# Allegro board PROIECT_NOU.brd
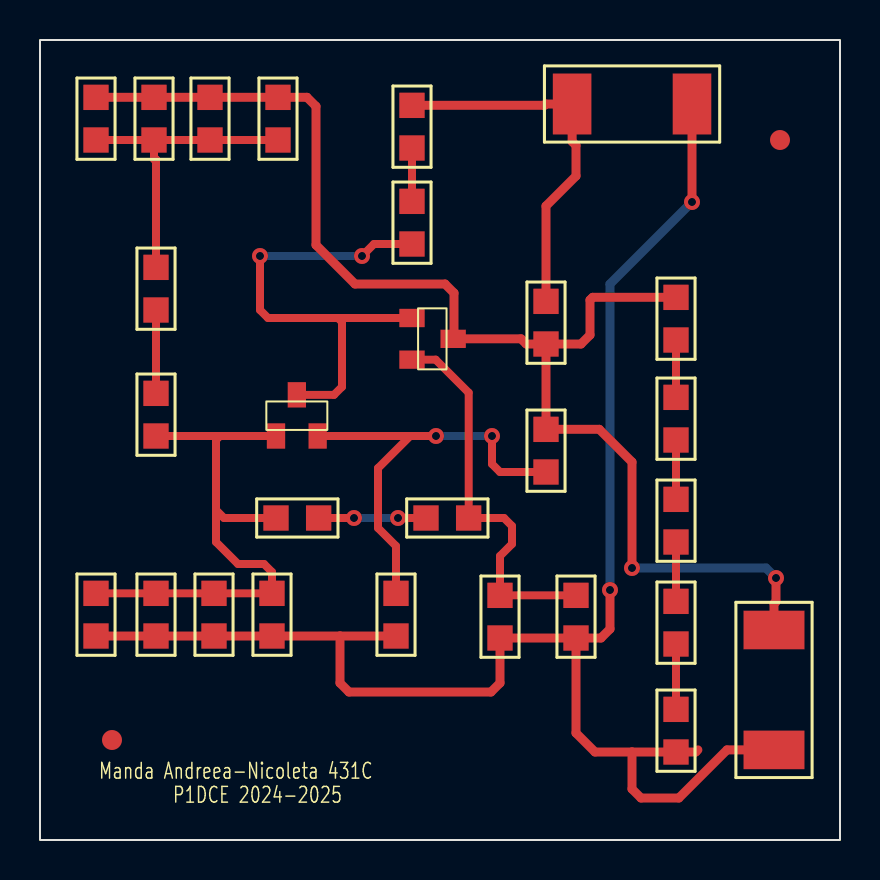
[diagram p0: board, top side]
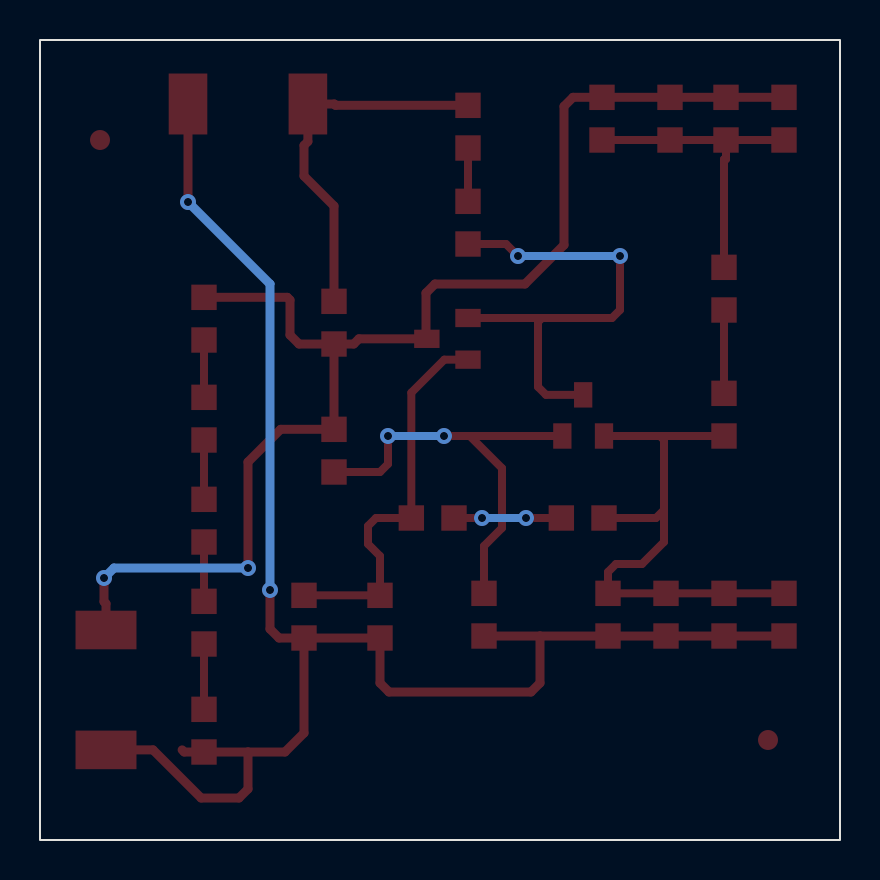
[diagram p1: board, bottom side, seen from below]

Outline 40 x 40 mm; copper layers: TOP, BOTTOM. Coordinates in mm from the lower left corner of the outline.
Outline path: rectangle 0,0 40,40

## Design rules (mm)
nets with their own width: min track width 0.4; nets N66424 N66434 N66454 N66462 N66620 N66652 N66792 N66798 N66804 N66810 N66814 N67108
nets with their own width: min track width 0.45; nets 0 V+ VO

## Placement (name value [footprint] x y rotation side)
C1  1n  [SMC0805]  31.8 25 90 top
C2  470p  [SMC0805]  8.5 35 90 top
C3  470p  [SMC0805]  8.7 10.2 90 top
C4  4.7u  [SMC0805]  26.8 10.1 90 top
C5  100p  [SMC0805]  5.8 10.2 90 top
C6  100p  [SMC0805]  11.6 10.2 90 top
C7  100p  [SMC0805]  2.8 10.2 90 top
C8  100p  [SMC0805]  11.9 35 90 top
C9  100p  [SMC0805]  5.7 35 90 top
C10  100p  [SMC0805]  2.8 35 90 top
J1  CON2  [SMR2512]  32.6 36.8 180 top
J2  CON2  [SMR2512]  36.7 10.5 270 top
NOREF  -  [unnamed]  3.6 5 0 top
NOREF#2  -  [unnamed]  37 35 0 top
Q7  QBC846B  [TO236AA]  18.6 26.1 180 top
Q8  QBC846B  [TO236AA]  11.8 20.2 270 top
R1  68  [SMR0805]  31.8 9.8 90 top
R2  2.2k  [SMR0805]  25.3 18.4 90 top
R4  10k  [SMR0805]  19.3 16.1 0 top
R6  3.9k  [SMR0805]  11.8 16.1 0 top
R7  680  [SMR0805]  23 10.1 90 top
R8  1k  [SMR0805]  17.8 10.2 90 top
R9  100  [SMR0805]  18.6 29.8 90 top
R10  2k  [SMR0805]  18.6 34.6 90 top
R11  680  [SMR0805]  25.3 24.8 90 top
R12  10k  [SMR0805]  5.8 20.2 90 top
R14  22  [SMR0805]  31.8 14.9 90 top
R15  510  [SMR0805]  31.8 20 90 top
R16  3.9k  [SMR0805]  5.8 26.5 90 top
R17  100  [SMR0805]  31.8 4.4 90 top

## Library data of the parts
C1-C10 = C
J1 J2 = CON2
Q7 = QBC846B_0
Q8 = QBC846B_1
R1 R2 R4 R6-R12 R14-R17 = R

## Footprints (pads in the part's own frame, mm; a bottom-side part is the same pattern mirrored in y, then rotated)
SMC0805
  rect 1.27x1.27 smd: 1(0,0) 2(2.134,0)
SMR0805
  rect 1.27x1.27 smd: 1(0,0) 2(2.134,0)
SMR2512
  rect 1.93x3.048 smd: 1(0,0) 2(5.994,0)
TO236AA
  rect 1.27x0.914 smd: 1(0,0) 2(0,2.083) 3(-2.057,1.041)
unnamed
  round 1 smd: (0,0)

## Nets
0: C3.1 C4.1 C5.1 C6.1 C7.1 J1.1 J2.2 R7.1 R8.1 R17.1
V+: J1.2 R10.2 R11.2
VO: C1.2 C2.2 C8.2 C9.2 C10.2 J2.1 Q7.3 R2.2 R11.1
N66424: Q8.2(E) R2.1 R8.2
N66434: R4.1 R6.2
N66454: C3.2 C5.2 C6.2 C7.2 Q8.1 R6.1 R12.1
N66462: Q7.1 Q8.3 R9.1
N66620: R9.2 R10.1
N66652: C4.2 Q7.2(E) R4.2 R7.2
N66792: R14.2 R15.1
N66798: C1.1 R15.2
N66804: R12.2 R16.1
N66810: C2.1 C8.1 C9.1 C10.1 R16.2
N66814: R1.2 R14.1
N67108: R1.1 R17.2

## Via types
v1: diameter 0.8, hole 0.4, TOP to BOTTOM, 10 vias

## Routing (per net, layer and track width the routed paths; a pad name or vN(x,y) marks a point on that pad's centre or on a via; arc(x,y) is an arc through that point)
0: length 83
  TOP w0.45: 15,10.2 15,7.85 15.45,7.4 22.55,7.4 23,7.85 R7.1 C4.1 ; 15,10.2 C6.1 C3.1 C5.1 C7.1 ; 15,10.2 R8.1 ; 29.6,4.4 R17.1 32.79,4.4 32.89,4.51 ; 29.6,4.4 29.6,2.55 30.05,2.1 31.94,2.1 34.35,4.51 J2.2 ; 29.6,4.4 27.75,4.4 26.8,5.35 C4.1 ; v1(28.5,12.5) 28.5,10.55 28.05,10.1 C4.1 ; v1(32.6,31.9) J1.1
  BOTTOM w0.45: v1(28.5,12.5) 28.5,27.8 v1(32.6,31.9)
V+: length 18.6
  TOP w0.45: R10.2 25.22,36.73 25.29,36.8 J1.2 26.61,34.92 26.8,34.73 26.8,33.2 25.3,31.7 R11.2
VO: length 66.2
  TOP w0.45: R11.1 27.05,24.8 27.5,25.25 27.5,27 27.63,27.13 C1.2 ; R11.1 R2.2 27.97,20.53 29.6,18.9 v1(29.6,13.6) ; R11.1 24.31,24.8 24.05,25.06 Q7.3 20.7,25.1 20.7,27.35 20.25,27.8 15.75,27.8 13.8,29.75 13.8,36.68 13.35,37.13 C8.2 C2.2 C9.2 C10.2 ; J2.1 36.7,11.82 36.8,11.92 v1(36.8,13.1)
  BOTTOM w0.45: v1(36.8,13.1) 36.3,13.6 v1(29.6,13.6)
N66424: length 21.9
  TOP w0.4: 18.51,20.2 Q8.2 ; 18.51,20.2 v1(19.8,20.2) ; 18.51,20.2 16.9,18.59 16.9,15.6 17.8,14.7 R8.2 ; v1(22.6,20.2) 22.6,18.8 23,18.4 R2.1
  BOTTOM w0.4: v1(19.8,20.2) v1(22.6,20.2)
N66434: length 5.4
  TOP w0.4: v1(15.7,16.1) R6.2 ; R4.1 v1(17.9,16.1)
  BOTTOM w0.4: v1(17.9,16.1) v1(15.7,16.1)
N66454: length 27.8
  TOP w0.4: R6.1 9.2,16.1 8.8,16.5 ; 8.8,16.5 8.8,14.9 9.9,13.8 11.2,13.8 11.6,13.4 C6.2 C3.2 C5.2 C7.2 ; 8.8,16.5 8.8,20 9,20.2 ; R12.1 9,20.2 ; 9,20.2 Q8.1
N66462: length 24.3
  TOP w0.4: v1(11,29.2) 11,26.5 11.4,26.1 14.9,26.1 ; Q8.3 14.7,22.26 15.1,22.66 15.1,25.9 14.9,26.1 ; v1(16.1,29.2) 16.7,29.8 R9.1 ; 14.9,26.1 Q7.1
  BOTTOM w0.4: v1(16.1,29.2) v1(11,29.2)
N66620: length 2.7
  TOP w0.4: R9.2 R10.1
N66652: length 19.6
  TOP w0.4: C4.2 R7.2 23,14.2 23.6,14.8 23.6,15.7 23.2,16.1 R4.2 21.43,22.37 19.78,24.02 Q7.2
N66792: length 3
  TOP w0.4: R15.1 R14.2
N66798: length 2.9
  TOP w0.4: C1.1 R15.2
N66804: length 4.2
  TOP w0.4: R16.1 R12.2
N66810: length 15.6
  TOP w0.4: C8.1 C2.1 C9.1 ; C10.1 C9.1 ; C9.1 5.7,34.04 5.8,34.04 R16.2
N66814: length 3
  TOP w0.4: R14.1 R1.2
N67108: length 3.3
  TOP w0.4: R1.1 R17.2

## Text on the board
Ref Des/Silkscreen Top: Manda Andreea-Nicoleta 431C | P1DCE 2024-2025
XSECTION_CHART: *  SURFACE | L1 TOP CONDUCTOR | *  DIELECTRIC | L2 BOTTOM CONDUCTOR | DESIGN CROSS SECTION CHART | ___________________________ | TOTAL THICKNESS 0.26416 MM | 1-2
NCLEGEND-1-2: FIGURE | FINISHED_SIZE | 0.4 | DRILL CHART: TOP to BOTTOM | ALL UNITS ARE IN MILLIMETERS | PLATED | QTY | 10
